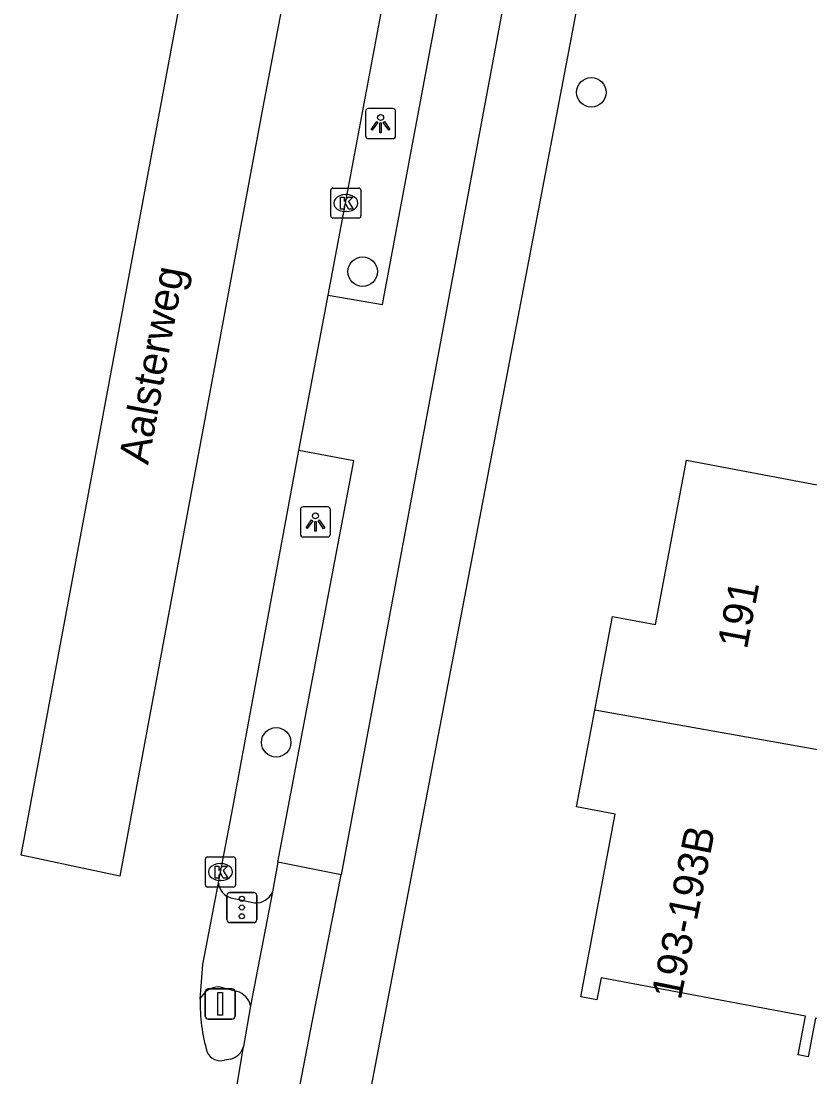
# Model space of a CAD drawing. Extents: x 161696 to 162377, y 380761 to 381673.
# Drawn here: x 161784.65 to 161810.83, y 381337.11 to 381372.14 of the extents above; entities that cross this region are included whole.
import ezdxf

# ---------------------------------------------------------------- set-up
doc = ezdxf.new("R2010")
doc.units = 0
for name, color, linetype in [('IMGEO_Boom', 7, 'Continuous'), ('IMGEO_Fietspad_gesloten', 7, 'Continuous'), ('IMGEO_Fietspad_open', 7, 'Continuous'), ('IMGEO_Kolk', 7, 'Continuous'), ('IMGEO_Lichtpunt', 7, 'Continuous'), ('IMGEO_Openbare_ruimte_label', 7, 'Continuous'), ('IMGEO_OVBaan_gesloten', 7, 'Continuous'), ('IMGEO_Pand', 7, 'Continuous'), ('IMGEO_Pand_nummerreeks', 7, 'Continuous'), ('IMGEO_Portaal', 7, 'Continuous'), ('IMGEO_Rijbaan_regionaal_gesloten', 7, 'Continuous'), ('IMGEO_Verkeersregelinstallatiepaal', 7, 'Continuous'), ('IMGEO_Voetpad_open', 7, 'Continuous')]:
    doc.layers.add(name, color=color, linetype=linetype)

msp = doc.modelspace()

# ---------------------------------------------------------------- linework, layer by layer
at = {"layer": 'IMGEO_Boom'}
for centre in [(161803.571, 381369.773), (161795.984, 381363.827), (161793.116, 381348.209)]:
    msp.add_circle(centre, 0.489, dxfattribs=at)
at = {"layer": 'IMGEO_Fietspad_gesloten'}
for points in [[(161793.173, 381344.238), (161792.987, 381343.25)], [(161795.276, 381343.812), (161793.173, 381344.238)], [(161793.853, 381336.576), (161794.32, 381338.986), (161795.276, 381343.812)], [(161792.987, 381343.25), (161792.266, 381339.472)], [(161792.266, 381339.472), (161792.027, 381338.124)]]:
    msp.add_lwpolyline(points, dxfattribs=at)
at = {"layer": 'IMGEO_Fietspad_open'}
for points in [[(161807.664, 381410.289), (161795.276, 381343.812)], [(161794.836, 381363.042), (161796.643, 381362.738), (161804.964, 381407.167), (161805.052, 381408.103)], [(161793.173, 381344.238), (161795.686, 381357.544), (161793.862, 381357.893)]]:
    msp.add_lwpolyline(points, dxfattribs=at)
at = {"layer": 'IMGEO_Kolk'}
for p, q in [((161794.925, 381365.674), (161794.925, 381366.526)), ((161795, 381366.6), (161795.852, 381366.6)), ((161795.926, 381366.526), (161795.926, 381365.674)), ((161795.413, 381366.38), (161795.438, 381366.38)), ((161795.436, 381365.82), (161795.411, 381365.82)), ((161795.852, 381365.6), (161795, 381365.6)), ((161790.84, 381344.408), (161791.692, 381344.408)), ((161790.765, 381343.482), (161790.765, 381344.334)), ((161791.253, 381344.188), (161791.278, 381344.188)), ((161791.766, 381344.334), (161791.766, 381343.482)), ((161791.692, 381343.408), (161790.84, 381343.408)), ((161791.276, 381343.628), (161791.251, 381343.628))]:
    msp.add_line(p, q, dxfattribs=at)
for points in [[(161794.925, 381365.674), (161794.925, 381366.526)], [(161795, 381366.6), (161795.852, 381366.6)], [(161795.926, 381366.526), (161795.926, 381365.674)], [(161795.246, 381366.3), (161795.369, 381366.3), (161795.369, 381366.149), (161795.499, 381366.3), (161795.663, 381366.3), (161795.517, 381366.149), (161795.67, 381365.9), (161795.518, 381365.9), (161795.433, 381366.064), (161795.369, 381365.997), (161795.369, 381365.9), (161795.246, 381365.9), (161795.246, 381366.3)], [(161795.852, 381365.6), (161795, 381365.6)], [(161790.84, 381344.408), (161791.692, 381344.408)], [(161790.765, 381343.482), (161790.765, 381344.334)], [(161791.086, 381344.108), (161791.209, 381344.108), (161791.209, 381343.957), (161791.339, 381344.108), (161791.503, 381344.108), (161791.357, 381343.957), (161791.51, 381343.708), (161791.358, 381343.708), (161791.273, 381343.872), (161791.209, 381343.805), (161791.209, 381343.708), (161791.086, 381343.708), (161791.086, 381344.108)], [(161791.766, 381344.334), (161791.766, 381343.482)], [(161791.692, 381343.408), (161790.84, 381343.408)]]:
    msp.add_lwpolyline(points, dxfattribs=at)
for centre, start, end in [((161795.002, 381366.524), 91.552, 178.448), ((161795.002, 381366.524), 91.552, 178.448), ((161795.85, 381366.524), 1.552, 88.448), ((161795.85, 381366.524), 1.552, 88.448), ((161795.002, 381365.676), 181.552, 268.448), ((161795.002, 381365.676), 181.552, 268.448), ((161795.85, 381365.676), 271.552, 358.448), ((161795.85, 381365.676), 271.552, 358.448), ((161790.842, 381344.332), 91.552, 178.448), ((161790.842, 381344.332), 91.552, 178.448), ((161791.69, 381344.332), 1.552, 88.448), ((161791.69, 381344.332), 1.552, 88.448), ((161790.842, 381343.484), 181.552, 268.448), ((161790.842, 381343.484), 181.552, 268.448), ((161791.69, 381343.484), 271.552, 358.448), ((161791.69, 381343.484), 271.552, 358.448)]:
    msp.add_arc(centre, 0.0765, start, end, dxfattribs=at)
for centre, major_axis, ratio, start_param, end_param in [((161795.412, 381366.1), (-0.387, 0.002), 0.722429, 4.712389, 7.853982), ((161795.437, 381366.1), (-0.39, 0.002), 0.717154, 1.570796, 4.712389), ((161791.252, 381343.908), (-0.387, 0.002), 0.722429, 4.712389, 7.853982), ((161791.277, 381343.908), (-0.39, 0.002), 0.717154, 1.570796, 4.712389)]:
    msp.add_ellipse(centre, major_axis=major_axis, ratio=ratio, start_param=start_param, end_param=end_param, dxfattribs=at)
at = {"layer": 'IMGEO_Lichtpunt'}
for p, q in [((161796.982, 381369.236), (161796.174, 381369.236)), ((161796.982, 381369.236), (161796.174, 381369.236)), ((161796.08, 381369.141), (161796.08, 381368.334)), ((161796.08, 381369.141), (161796.08, 381368.334)), ((161797.076, 381368.334), (161797.076, 381369.141)), ((161797.076, 381368.334), (161797.076, 381369.141)), ((161796.174, 381368.24), (161796.982, 381368.24)), ((161796.174, 381368.24), (161796.982, 381368.24)), ((161793.918, 381355.926), (161793.918, 381355.119)), ((161793.918, 381355.926), (161793.918, 381355.119)), ((161794.82, 381356.021), (161794.012, 381356.021)), ((161794.82, 381356.021), (161794.012, 381356.021)), ((161794.914, 381355.119), (161794.914, 381355.926)), ((161794.914, 381355.119), (161794.914, 381355.926)), ((161794.012, 381355.025), (161794.82, 381355.025)), ((161794.012, 381355.025), (161794.82, 381355.025))]:
    msp.add_line(p, q, dxfattribs=at)
for points in [[(161796.454, 381368.805), (161796.493, 381368.777), (161796.305, 381368.515), (161796.267, 381368.542), (161796.454, 381368.805)], [(161796.556, 381368.757), (161796.603, 381368.757), (161796.603, 381368.435), (161796.556, 381368.435), (161796.556, 381368.757)], [(161796.666, 381368.777), (161796.704, 381368.804), (161796.891, 381368.542), (161796.852, 381368.514), (161796.666, 381368.777)], [(161794.292, 381355.59), (161794.331, 381355.562), (161794.143, 381355.3), (161794.105, 381355.327), (161794.292, 381355.59)], [(161794.504, 381355.562), (161794.542, 381355.589), (161794.729, 381355.327), (161794.69, 381355.299), (161794.504, 381355.562)], [(161794.394, 381355.542), (161794.441, 381355.542), (161794.441, 381355.22), (161794.394, 381355.22), (161794.394, 381355.542)]]:
    msp.add_lwpolyline(points, dxfattribs=at)
for centre in [(161796.579, 381368.939), (161794.417, 381355.724)]:
    msp.add_circle(centre, 0.0994, dxfattribs=at)
for centre, start, end in [((161796.174, 381369.141), 90, 180), ((161796.174, 381369.141), 90, 180), ((161796.982, 381369.141), 0, 90), ((161796.982, 381369.141), 0, 90), ((161796.174, 381368.334), 180, 270), ((161796.174, 381368.334), 180, 270), ((161796.982, 381368.334), 270, 0), ((161796.982, 381368.334), 270, 360), ((161794.012, 381355.926), 90, 180), ((161794.012, 381355.926), 90, 180), ((161794.82, 381355.926), 0, 90), ((161794.82, 381355.926), 0, 90), ((161794.012, 381355.119), 180, 270), ((161794.012, 381355.119), 180, 270), ((161794.82, 381355.119), 270, 0), ((161794.82, 381355.119), 270, 360)]:
    msp.add_arc(centre, 0.0946, start, end, dxfattribs=at)
at = {"layer": 'IMGEO_OVBaan_gesloten'}
msp.add_lwpolyline([(161800.748, 381411.707), (161792.667, 381369.279), (161787.923, 381343.771), (161784.65, 381344.468), (161792.662, 381387.441), (161797.183, 381412.205), (161800.748, 381411.707)], dxfattribs=at)
at = {"layer": 'IMGEO_Pand'}
for points in [[(161803.684, 381349.278), (161804.27, 381352.387), (161805.701, 381352.117), (161806.73, 381357.569), (161811.48, 381356.673), (161811.685, 381357.754), (161813.746, 381357.364), (161814.024, 381358.833), (161822.539, 381357.222), (161821.045, 381349.322), (161821.831, 381349.174), (161821.683, 381348.388), (161821.4, 381345.98)], [(161821.4, 381345.98), (161820.772, 381342.965), (161820.027, 381343.046), (161818.792, 381336.562), (161819.578, 381336.412), (161819.512, 381336.069), (161813.321, 381337.248), (161813.574, 381338.574), (161811.011, 381339.058), (161810.768, 381337.776), (161810.434, 381337.84), (161810.677, 381339.122), (161803.897, 381340.403), (161803.757, 381339.665), (161803.22, 381339.768), (161804.366, 381345.83), (161803.078, 381346.073), (161803.684, 381349.278)], [(161821.4, 381345.98), (161819.76, 381346.526), (161811.027, 381347.977), (161803.684, 381349.278)]]:
    msp.add_lwpolyline(points, dxfattribs=at)
at = {"layer": 'IMGEO_Portaal'}
for p, q in [((161790.758, 381339.132), (161790.758, 381339.932)), ((161790.758, 381339.932), (161790.758, 381339.132)), ((161790.858, 381340.032), (161791.648, 381340.032)), ((161791.648, 381340.032), (161790.858, 381340.032)), ((161791.748, 381339.932), (161791.748, 381339.132)), ((161791.748, 381339.132), (161791.748, 381339.932)), ((161791.648, 381339.032), (161790.858, 381339.032)), ((161790.858, 381339.032), (161791.648, 381339.032))]:
    msp.add_line(p, q, dxfattribs=at)
msp.add_lwpolyline([(161791.178, 381339.907), (161791.328, 381339.907), (161791.328, 381339.157), (161791.178, 381339.157), (161791.178, 381339.907)], dxfattribs=at)
for centre, start, end in [((161790.858, 381339.932), 90, 180), ((161790.858, 381339.932), 90, 180), ((161791.648, 381339.932), 0, 90), ((161791.648, 381339.932), 360, 90), ((161790.858, 381339.132), 180, 270), ((161790.858, 381339.132), 180, 270), ((161791.648, 381339.132), 270, 0), ((161791.648, 381339.132), 270, 0)]:
    msp.add_arc(centre, 0.1, start, end, dxfattribs=at)
at = {"layer": 'IMGEO_Rijbaan_regionaal_gesloten'}
for points in [[(161794.836, 381363.042), (161795.42, 381366.1), (161799.73, 381389.111), (161802.374, 381403.439), (161802.88, 381406.207), (161803.329, 381408.577)], [(161793.862, 381357.893), (161794.836, 381363.042)], [(161791.197, 381343.554), (161791.671, 381346.043), (161793.862, 381357.893)], [(161790.595, 381339.692), (161790.683, 381340.84), (161791.197, 381343.554)], [(161789.248, 381321.366), (161792.027, 381338.124)], [(161791.608, 381337.705), (161791.403, 381337.67)]]:
    msp.add_lwpolyline(points, dxfattribs=at)
for centre, radius, start, end in [((161796.12, 381339.52), 5.527, 178.2152, 196.6838), ((161791.47, 381338.262), 0.574, 283.9189, 346.0811), ((161791.262, 381338.128), 0.479, 204.008, 287.0593)]:
    msp.add_arc(centre, radius, start, end, dxfattribs=at)
at = {"layer": 'IMGEO_Verkeersregelinstallatiepaal'}
for p, q in [((161791.479, 381342.331), (161791.479, 381343.131)), ((161791.479, 381343.131), (161791.479, 381342.331)), ((161791.579, 381343.231), (161792.369, 381343.231)), ((161792.369, 381343.231), (161791.579, 381343.231)), ((161792.469, 381343.131), (161792.469, 381342.331)), ((161792.469, 381342.331), (161792.469, 381343.131)), ((161792.369, 381342.231), (161791.579, 381342.231)), ((161791.579, 381342.231), (161792.369, 381342.231))]:
    msp.add_line(p, q, dxfattribs=at)
for centre in [(161791.974, 381343.021), (161791.974, 381342.731), (161791.974, 381342.441)]:
    msp.add_circle(centre, 0.085, dxfattribs=at)
for centre, start, end in [((161791.579, 381343.131), 90, 180), ((161791.579, 381343.131), 90, 180), ((161792.369, 381343.131), 0, 90), ((161792.369, 381343.131), 360, 90), ((161791.579, 381342.331), 180, 270), ((161791.579, 381342.331), 180, 270), ((161792.369, 381342.331), 270, 0), ((161792.369, 381342.331), 270, 0)]:
    msp.add_arc(centre, 0.1, start, end, dxfattribs=at)
at = {"layer": 'IMGEO_Voetpad_open'}
for points in [[(161810.056, 381409.956), (161802.946, 381371.822), (161796.224, 381336.573)], [(161791.612, 381343.049), (161792.398, 381342.884)], [(161791.814, 381339.948), (161791.215, 381340.096)]]:
    msp.add_lwpolyline(points, dxfattribs=at)
for centre, radius, start, end in [((161791.778, 381343.608), 0.583, 185.3253, 253.5002), ((161792.441, 381343.471), 0.589, 265.7712, 337.9417), ((161791.203, 381339.436), 0.66, 88.9983, 157.1793), ((161791.63, 381339.321), 0.653, 13.3652, 73.6719)]:
    msp.add_arc(centre, radius, start, end, dxfattribs=at)

# ---------------------------------------------------------------- texts
at = {"layer": 'IMGEO_Openbare_ruimte_label'}
msp.add_text('Aalsterweg', height=1, rotation=79.4543, dxfattribs=at).set_placement((161788.864, 381357.394))
at = {"layer": 'IMGEO_Pand_nummerreeks'}
for s, rotation, p in [('191', 79.2906, (161808.734, 381351.271)), ('193-193B', 78.5729, (161806.539, 381339.632))]:
    msp.add_text(s, height=1, rotation=rotation, dxfattribs=at).set_placement(p)

doc.saveas('drawing.dxf')
